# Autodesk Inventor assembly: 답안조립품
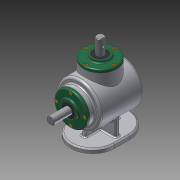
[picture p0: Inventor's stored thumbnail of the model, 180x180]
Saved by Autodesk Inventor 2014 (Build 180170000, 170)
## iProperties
Created: 2016-04
Part Number: 답안조립품
Document SubType Name: Assembly
Designer: user
Author: user
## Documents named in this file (14)
- C:\Users\user\Desktop\460408V1013\답안조립품.iam
- C:\Users\user\Desktop\460408V1013\본체.ipt
- C:\Users\user\Desktop\460408V1013\커버.ipt
- C:\Users\user\Desktop\460408V1013\M4.ipt
- C:\Users\user\Desktop\460408V1013\오일실 17 32 8.ipt
- C:\Users\user\Desktop\460408V1013\메인 축.ipt
- 메인 축.ipt
- C:\Users\user\Desktop\460408V1013\키 5x5.ipt
- C:\Users\user\Desktop\460408V1013\메인 베벨기어.ipt
- C:\Users\user\Desktop\460408V1013\베어링 6203.ipt
- C:\Users\user\Desktop\460408V1013\서브 축.ipt
- 서브 축.ipt
- C:\Users\user\Desktop\460408V1013\키 4x4.ipt
- C:\Users\user\Desktop\460408V1013\서브 베벨기어.ipt
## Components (8 placed, 1 different names)
1. M4:3 — Insert:4
2. M4:4
3. M4:5
4. M4:6
5. M4:2 — Insert:3
6. M4:7
7. M4:8
8. M4:9
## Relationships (2: Insert 2)
- Insert:3: M4:2
- Insert:4: M4:3
